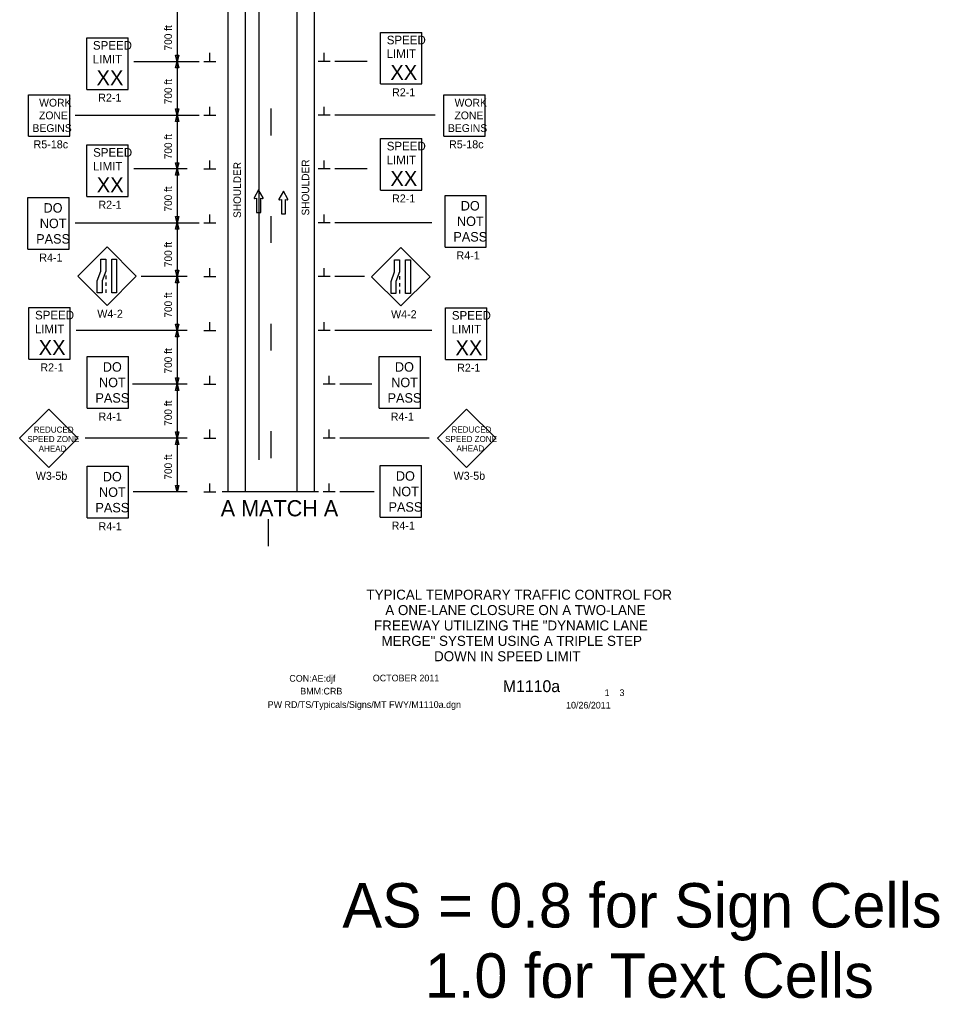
# Model space of a CAD drawing. Extents: x 15261 to 18126, y 1908 to 6555.
# Drawn here: x 15359 to 16214, y 1908 to 2818 of the extents above; entities that cross this region are included whole.
import ezdxf

# ---------------------------------------------------------------- set-up
doc = ezdxf.new("R2010")
doc.units = 0
for name, color, linetype in [('ALI_LEGAL_EX', 7, 'Continuous'), ('BORDER_SIGNAL_WO', 7, 'Continuous'), ('MT_SCRATCH_LEVEL_E', 7, 'Continuous'), ('PAVT_EDGE_EX', 7, 'Continuous'), ('TRAFFIC_SIGNS_PR', 7, 'Continuous'), ('TYPICAL_TEXT_DIMEN_PR', 7, 'Continuous')]:
    doc.layers.add(name, color=color, linetype=linetype)

msp = doc.modelspace()

# ---------------------------------------------------------------- linework, layer by layer
at = {"layer": 'ALI_LEGAL_EX'}
msp.add_line((15581.68, 3237.79), (15581.68, 2408.6), dxfattribs=at)
for points in [[(15593, 2735), (15593, 2710)], [(15593, 2635), (15593, 2610)], [(15593, 2535), (15593, 2510)], [(15593, 2435), (15593, 2410)], [(15590.81, 2328.27), (15590.81, 2353.27)]]:
    msp.add_lwpolyline(points, dxfattribs=at)
at = {"layer": 'MT_SCRATCH_LEVEL_E'}
for p, q in [((15581.51, 2659.29), (15577.39, 2652.05)), ((15585.65, 2652.05), (15581.51, 2659.29)), ((15604.48, 2658.02), (15600.37, 2650.78)), ((15608.63, 2650.78), (15604.48, 2658.02)), ((15577.88, 2651.37), (15579.65, 2651.68)), ((15579.65, 2651.68), (15579.65, 2638.43)), ((15583.4, 2638.43), (15583.4, 2651.68)), ((15583.4, 2651.68), (15585.17, 2651.37)), ((15600.85, 2650.1), (15602.63, 2650.41)), ((15602.63, 2650.41), (15602.63, 2637.16)), ((15606.37, 2637.16), (15606.37, 2650.41)), ((15606.37, 2650.41), (15608.15, 2650.1)), ((15579.65, 2638.43), (15583.4, 2638.43)), ((15602.63, 2637.16), (15606.37, 2637.16))]:
    msp.add_line(p, q, dxfattribs=at)
for centre, start, end in [((15577.8, 2651.83), 150.42484, 279.96381), ((15585.24, 2651.83), 260.03619, 29.77312), ((15600.78, 2650.56), 150.42484, 279.96381), ((15608.22, 2650.56), 260.03619, 29.77312)]:
    msp.add_arc(centre, 0.463, start, end, dxfattribs=at)
at = {"layer": 'PAVT_EDGE_EX'}
for p, q in [((15553, 3162.29), (15553, 2378.74)), ((15569, 3162.29), (15569, 2378.74)), ((15617, 3162.29), (15617, 2378.74)), ((15633, 3163.21), (15633, 2378.74))]:
    msp.add_line(p, q, dxfattribs=at)
at = {"layer": 'TRAFFIC_SIGNS_PR'}
for p, q in [((15694.86, 2805.71), (15733.26, 2805.71)), ((15694.86, 2757.71), (15694.86, 2805.71)), ((15733.26, 2757.71), (15733.26, 2805.71)), ((15421.69, 2800.74), (15460.09, 2800.74)), ((15421.69, 2752.74), (15421.69, 2800.74)), ((15460.09, 2752.74), (15460.09, 2800.74)), ((15694.86, 2757.71), (15733.26, 2757.71)), ((15367.49, 2709.37), (15367.49, 2747.77)), ((15367.49, 2747.77), (15405.89, 2747.77)), ((15405.89, 2709.37), (15405.89, 2747.77)), ((15421.69, 2752.74), (15460.09, 2752.74)), ((15753.7, 2709.37), (15753.7, 2747.77)), ((15753.7, 2747.77), (15792.1, 2747.77)), ((15792.1, 2709.37), (15792.1, 2747.77)), ((15367.49, 2709.37), (15405.89, 2709.37)), ((15421.89, 2701.27), (15460.29, 2701.27)), ((15421.89, 2653.27), (15421.89, 2701.27)), ((15460.29, 2653.27), (15460.29, 2701.27)), ((15694.86, 2707.12), (15733.26, 2707.12)), ((15694.86, 2659.12), (15694.86, 2707.12)), ((15733.26, 2659.12), (15733.26, 2707.12)), ((15753.7, 2709.37), (15792.1, 2709.37)), ((15694.86, 2659.12), (15733.26, 2659.12)), ((15366.92, 2604.2), (15366.92, 2652.2)), ((15366.92, 2652.2), (15405.32, 2652.2)), ((15405.32, 2604.2), (15405.32, 2652.2)), ((15421.89, 2653.27), (15460.29, 2653.27)), ((15754.76, 2606.14), (15754.76, 2654.14)), ((15754.76, 2654.14), (15793.16, 2654.14)), ((15793.16, 2606.14), (15793.16, 2654.14)), ((15366.92, 2604.2), (15405.32, 2604.2)), ((15440.58, 2606.28), (15413.42, 2579.12)), ((15467.73, 2579.12), (15440.58, 2606.28)), ((15713.65, 2605.8), (15686.5, 2578.65)), ((15740.81, 2578.65), (15713.65, 2605.8)), ((15754.76, 2606.14), (15793.16, 2606.14)), ((15413.42, 2579.12), (15440.58, 2551.97)), ((15439.33, 2579.62), (15439.33, 2576.42)), ((15440.58, 2551.97), (15467.73, 2579.12)), ((15686.5, 2578.65), (15713.65, 2551.49)), ((15712.41, 2579.14), (15712.41, 2575.94)), ((15713.65, 2551.49), (15740.81, 2578.65)), ((15439.33, 2573.22), (15439.33, 2570.02)), ((15439.33, 2566.82), (15439.33, 2563.62)), ((15712.41, 2572.74), (15712.41, 2569.54)), ((15712.41, 2566.34), (15712.41, 2563.14)), ((15367.92, 2550.12), (15406.32, 2550.12)), ((15367.92, 2502.12), (15367.92, 2550.12)), ((15406.32, 2502.12), (15406.32, 2550.12)), ((15755.36, 2549.85), (15793.76, 2549.85)), ((15755.36, 2501.85), (15755.36, 2549.85)), ((15793.76, 2501.85), (15793.76, 2549.85)), ((15367.92, 2502.12), (15406.32, 2502.12)), ((15422.01, 2456.41), (15422.01, 2504.41)), ((15422.01, 2504.41), (15460.41, 2504.41)), ((15460.41, 2456.41), (15460.41, 2504.41)), ((15693.58, 2456.41), (15693.58, 2504.41)), ((15693.58, 2504.41), (15731.98, 2504.41)), ((15731.98, 2456.41), (15731.98, 2504.41)), ((15755.36, 2501.85), (15793.76, 2501.85)), ((15422.01, 2456.41), (15460.41, 2456.41)), ((15693.58, 2456.41), (15731.98, 2456.41)), ((15774.79, 2455.71), (15747.64, 2428.56)), ((15801.94, 2428.56), (15774.79, 2455.71)), ((15386.43, 2455.66), (15359.28, 2428.51)), ((15413.58, 2428.51), (15386.43, 2455.66)), ((15359.28, 2428.51), (15386.43, 2401.35)), ((15386.43, 2401.35), (15413.58, 2428.51)), ((15747.64, 2428.56), (15774.79, 2401.4)), ((15774.79, 2401.4), (15801.94, 2428.56)), ((15422.01, 2354.46), (15422.01, 2402.46)), ((15422.01, 2402.46), (15460.41, 2402.46)), ((15460.41, 2354.46), (15460.41, 2402.46)), ((15694.47, 2355.09), (15694.47, 2403.09)), ((15694.47, 2403.09), (15732.87, 2403.09)), ((15732.87, 2355.09), (15732.87, 2403.09)), ((15422.01, 2354.46), (15460.41, 2354.46)), ((15694.47, 2355.09), (15732.87, 2355.09))]:
    msp.add_line(p, q, dxfattribs=at)
for points in [[(15439.33, 2594.86), (15439.33, 2583.68), (15435.99, 2574.8), (15435.99, 2563.62), (15431.49, 2563.62), (15431.49, 2574.8), (15434.84, 2583.68), (15434.84, 2594.86)], [(15449.47, 2594.86), (15449.47, 2563.62), (15444.97, 2563.62), (15444.97, 2594.86)], [(15712.41, 2594.38), (15712.41, 2583.2), (15709.06, 2574.32), (15709.06, 2563.14), (15704.57, 2563.14), (15704.57, 2574.32), (15707.91, 2583.2), (15707.91, 2594.38)], [(15722.54, 2594.38), (15722.54, 2563.14), (15718.05, 2563.14), (15718.05, 2594.38)]]:
    msp.add_lwpolyline(points, close=True, dxfattribs=at)
at = {"layer": 'TYPICAL_TEXT_DIMEN_PR'}
for p, q in [((15505.88, 2828.74), (15505.88, 2778.74)), ((15505.88, 2778.74), (15504.31, 2784.61)), ((15504.31, 2784.61), (15505.88, 2784.61)), ((15505.88, 2784.61), (15507.45, 2784.61)), ((15507.45, 2784.61), (15505.88, 2778.74)), ((15536.12, 2778.74), (15536.12, 2786.53)), ((15642.37, 2778.74), (15642.37, 2786.53)), ((15465.47, 2778.74), (15526.25, 2778.74)), ((15504.31, 2772.88), (15505.88, 2778.74)), ((15504.31, 2772.88), (15505.88, 2778.74)), ((15505.88, 2778.74), (15505.88, 2728.74)), ((15505.88, 2778.74), (15507.45, 2772.88)), ((15505.88, 2778.74), (15507.45, 2772.88)), ((15530.5, 2778.74), (15541.75, 2778.74)), ((15648, 2778.74), (15636.75, 2778.74)), ((15682.48, 2778.74), (15652.25, 2778.74)), ((15505.88, 2772.88), (15504.31, 2772.88)), ((15505.88, 2772.88), (15504.31, 2772.88)), ((15507.45, 2772.88), (15505.88, 2772.88)), ((15507.45, 2772.88), (15505.88, 2772.88)), ((15410.88, 2728.74), (15526.25, 2728.74)), ((15505.88, 2728.74), (15504.31, 2734.61)), ((15504.31, 2734.61), (15505.88, 2734.61)), ((15505.88, 2728.74), (15504.31, 2734.61)), ((15504.31, 2734.61), (15505.88, 2734.61)), ((15504.31, 2722.88), (15505.88, 2728.74)), ((15505.88, 2734.61), (15507.45, 2734.61)), ((15507.45, 2734.61), (15505.88, 2728.74)), ((15505.88, 2734.61), (15507.45, 2734.61)), ((15507.45, 2734.61), (15505.88, 2728.74)), ((15505.88, 2728.74), (15505.88, 2678.74)), ((15505.88, 2728.74), (15507.45, 2722.88)), ((15530.5, 2728.74), (15541.75, 2728.74)), ((15536.12, 2728.74), (15536.12, 2736.53)), ((15648, 2728.74), (15636.75, 2728.74)), ((15642.37, 2728.74), (15642.37, 2736.53)), ((15745.66, 2728.74), (15652.25, 2728.74)), ((15505.88, 2722.88), (15504.31, 2722.88)), ((15507.45, 2722.88), (15505.88, 2722.88)), ((15505.88, 2678.74), (15504.31, 2684.61)), ((15504.31, 2684.61), (15505.88, 2684.61)), ((15505.88, 2684.61), (15507.45, 2684.61)), ((15507.45, 2684.61), (15505.88, 2678.74)), ((15536.12, 2678.74), (15536.12, 2686.53)), ((15642.37, 2678.74), (15642.37, 2686.53)), ((15515.11, 2678.74), (15465.47, 2678.74)), ((15504.31, 2672.88), (15505.88, 2678.74)), ((15505.88, 2678.74), (15505.88, 2628.74)), ((15505.88, 2678.74), (15507.45, 2672.88)), ((15530.5, 2678.74), (15541.75, 2678.74)), ((15648, 2678.74), (15636.75, 2678.74)), ((15682.48, 2678.74), (15652.25, 2678.74)), ((15505.88, 2672.88), (15504.31, 2672.88)), ((15507.45, 2672.88), (15505.88, 2672.88)), ((15410.88, 2628.74), (15526.25, 2628.74)), ((15505.88, 2628.74), (15504.31, 2634.61)), ((15504.31, 2634.61), (15505.88, 2634.61)), ((15505.88, 2628.74), (15504.31, 2634.61)), ((15504.31, 2634.61), (15505.88, 2634.61)), ((15504.31, 2622.88), (15505.88, 2628.74)), ((15505.88, 2634.61), (15507.45, 2634.61)), ((15507.45, 2634.61), (15505.88, 2628.74)), ((15505.88, 2634.61), (15507.45, 2634.61)), ((15507.45, 2634.61), (15505.88, 2628.74)), ((15505.88, 2628.74), (15505.88, 2578.74)), ((15505.88, 2628.74), (15507.45, 2622.88)), ((15530.5, 2628.74), (15541.75, 2628.74)), ((15536.12, 2628.74), (15536.12, 2636.53)), ((15648, 2628.74), (15636.75, 2628.74)), ((15642.37, 2628.74), (15642.37, 2636.53)), ((15742.5, 2628.74), (15652.25, 2628.74)), ((15505.88, 2622.88), (15504.31, 2622.88)), ((15507.45, 2622.88), (15505.88, 2622.88)), ((15505.88, 2578.74), (15504.31, 2584.61)), ((15504.31, 2584.61), (15505.88, 2584.61)), ((15505.88, 2584.61), (15507.45, 2584.61)), ((15507.45, 2584.61), (15505.88, 2578.74)), ((15536.12, 2578.74), (15536.12, 2586.53)), ((15642.37, 2578.74), (15642.37, 2586.53)), ((15515.11, 2578.74), (15472.22, 2578.74)), ((15504.31, 2572.88), (15505.88, 2578.74)), ((15505.88, 2578.74), (15507.45, 2572.88)), ((15505.88, 2578.74), (15505.88, 2528.74)), ((15530.5, 2578.74), (15541.75, 2578.74)), ((15648, 2578.74), (15636.75, 2578.74)), ((15679.85, 2578.74), (15652.25, 2578.74)), ((15505.88, 2572.88), (15504.31, 2572.88)), ((15507.45, 2572.88), (15505.88, 2572.88)), ((15515.11, 2528.74), (15411.99, 2528.74)), ((15505.88, 2528.74), (15504.31, 2534.61)), ((15504.31, 2534.61), (15505.88, 2534.61)), ((15504.31, 2522.88), (15505.88, 2528.74)), ((15505.88, 2534.61), (15507.45, 2534.61)), ((15507.45, 2534.61), (15505.88, 2528.74)), ((15505.88, 2528.74), (15507.45, 2522.88)), ((15505.88, 2528.74), (15505.88, 2478.74)), ((15530.5, 2528.74), (15541.75, 2528.74)), ((15536.12, 2528.74), (15536.12, 2536.53)), ((15648, 2528.74), (15636.75, 2528.74)), ((15642.37, 2528.74), (15642.37, 2536.53)), ((15742.5, 2528.74), (15652.25, 2528.74)), ((15505.88, 2522.88), (15504.31, 2522.88)), ((15507.45, 2522.88), (15505.88, 2522.88)), ((15505.88, 2478.74), (15504.31, 2484.61)), ((15504.31, 2484.61), (15505.88, 2484.61)), ((15505.88, 2484.61), (15507.45, 2484.61)), ((15507.45, 2484.61), (15505.88, 2478.74)), ((15536.12, 2478.74), (15536.12, 2486.53)), ((15647.13, 2478.74), (15647.13, 2486.53)), ((15515.11, 2478.74), (15464.24, 2478.74)), ((15504.31, 2472.88), (15505.88, 2478.74)), ((15505.88, 2478.74), (15507.45, 2472.88)), ((15505.88, 2478.74), (15505.88, 2428.74)), ((15530.5, 2478.74), (15541.75, 2478.74)), ((15652.75, 2478.74), (15641.5, 2478.74)), ((15686.65, 2478.74), (15657.07, 2478.74)), ((15505.88, 2472.88), (15504.31, 2472.88)), ((15507.45, 2472.88), (15505.88, 2472.88)), ((15515.11, 2428.74), (15420.33, 2428.74)), ((15505.88, 2428.74), (15504.31, 2434.61)), ((15504.31, 2434.61), (15505.88, 2434.61)), ((15504.31, 2422.88), (15505.88, 2428.74)), ((15505.88, 2434.61), (15507.45, 2434.61)), ((15507.45, 2434.61), (15505.88, 2428.74)), ((15505.88, 2428.74), (15507.45, 2422.88)), ((15505.88, 2428.74), (15505.88, 2378.74)), ((15530.5, 2428.74), (15541.75, 2428.74)), ((15536.12, 2428.74), (15536.12, 2436.53)), ((15652.75, 2428.74), (15641.5, 2428.74)), ((15647.13, 2428.74), (15647.13, 2436.53)), ((15740.14, 2428.74), (15657.07, 2428.74)), ((15505.88, 2422.88), (15504.31, 2422.88)), ((15507.45, 2422.88), (15505.88, 2422.88)), ((15505.88, 2378.74), (15504.31, 2384.61)), ((15504.31, 2384.61), (15505.88, 2384.61)), ((15505.88, 2384.61), (15507.45, 2384.61)), ((15507.45, 2384.61), (15505.88, 2378.74)), ((15536.12, 2378.74), (15536.12, 2386.53)), ((15647.13, 2378.74), (15647.13, 2386.53)), ((15515.11, 2378.74), (15464.95, 2378.74)), ((15530.5, 2378.74), (15541.75, 2378.74)), ((15637.19, 2378.74), (15547.76, 2378.74)), ((15652.75, 2378.74), (15641.5, 2378.74)), ((15688.96, 2378.74), (15657.07, 2378.74))]:
    msp.add_line(p, q, dxfattribs=at)

# ---------------------------------------------------------------- texts
at = {"layer": 'BORDER_SIGNAL_WO'}
for s, height, p in [('TYPICAL TEMPORARY TRAFFIC CONTROL FOR', 9.3, (15681.73, 2278.54)), ('A ONE-LANE CLOSURE ON A TWO-LANE', 9.3, (15699.24, 2264.24)), ('FREEWAY UTILIZING THE "DYNAMIC LANE', 9.3, (15688.74, 2249.94)), ('MERGE" SYSTEM USING A TRIPLE STEP', 9.3, (15695.73, 2235.64)), ('DOWN IN SPEED LIMIT', 9.3, (15744.6, 2221.34)), ('CON:AE:djf  ', 6.2, (15610.05, 2202.35)), ('    OCTOBER 2011    ', 6.2, (15678.44, 2202.63)), ('    M1110a   ', 11, (15792.22, 2192.67)), ('BMM:CRB   ', 6.2, (15620.17, 2190.46)), (' 1    3 ', 6.2, (15900.81, 2188.99)), ('PW RD/TS/Typicals/Signs/MT FWY/M1110a.dgn      ', 6.2, (15589.92, 2178)), ('10/26/2011    ', 6.2, (15867.29, 2177.42)), ('AS = 0.8 for Sign Cells', 41.2877, (15659.37, 1973.92)), ('     1.0 for Text Cells', 41.2877, (15659.37, 1908.64))]:
    msp.add_text(s, height=height, dxfattribs=at).set_placement(p)
at = {"layer": 'TRAFFIC_SIGNS_PR'}
for s, height, p in [('SPEED', 8, (15700.63, 2794.58)), ('SPEED', 8, (15427.45, 2789.6)), ('LIMIT', 8, (15427.29, 2776.8)), ('LIMIT', 8, (15700.47, 2781.78)), ('XX', 14.031, (15703.97, 2761.47)), ('XX', 14.031, (15430.8, 2756.5)), ('R2-1', 7.44, (15432.36, 2741.3)), ('R2-1', 7.44, (15705.54, 2746.27)), ('WORK', 7.217, (15377.49, 2736.74)), ('WORK', 7.217, (15763.7, 2736.74)), ('ZONE', 7.217, (15377.37, 2724.93)), ('ZONE', 7.217, (15763.58, 2724.93)), ('BEGINS', 7.217, (15371.3, 2713.12)), ('BEGINS', 7.217, (15757.51, 2713.12)), ('R5-18c', 7.44, (15372.3, 2697.93)), ('SPEED', 8, (15700.63, 2695.99)), ('R5-18c', 7.44, (15758.51, 2697.93)), ('SPEED', 8, (15427.66, 2690.14)), ('LIMIT', 8, (15427.5, 2677.34)), ('LIMIT', 8, (15700.47, 2683.19)), ('XX', 14.031, (15703.97, 2662.88)), ('XX', 14.031, (15431, 2657.03)), ('DO', 8.8, (15381.55, 2638.2)), ('R2-1', 7.44, (15432.57, 2641.83)), ('R2-1', 7.44, (15705.54, 2647.68)), ('DO', 8.8, (15769.39, 2640.15)), ('NOT', 8.8, (15378.07, 2623.8)), ('NOT', 8.8, (15765.9, 2625.75)), ('PASS', 8.8, (15762.55, 2611.35)), ('PASS', 8.8, (15374.72, 2609.4)), ('R4-1', 7.44, (15765.44, 2594.71)), ('R4-1', 7.44, (15377.6, 2592.76)), ('SPEED', 8, (15373.68, 2538.98)), ('W4-2', 7.44, (15431.53, 2540.53)), ('W4-2', 7.44, (15704.61, 2540.06)), ('SPEED', 8, (15761.13, 2538.71)), ('LIMIT', 8, (15373.52, 2526.18)), ('LIMIT', 8, (15760.97, 2525.91)), ('XX', 14.031, (15377.03, 2505.88)), ('XX', 14.031, (15764.47, 2505.61)), ('R2-1', 7.44, (15378.59, 2490.68)), ('DO', 8.8, (15436.65, 2490.41)), ('DO', 8.8, (15708.21, 2490.41)), ('R2-1', 7.44, (15766.04, 2490.41)), ('NOT', 8.8, (15433.16, 2476.01)), ('NOT', 8.8, (15704.73, 2476.01)), ('PASS', 8.8, (15429.81, 2461.62)), ('PASS', 8.8, (15701.38, 2461.62)), ('R4-1', 7.44, (15432.69, 2444.97)), ('R4-1', 7.44, (15704.26, 2444.97)), ('REDUCED', 5.6, (15372.49, 2433.81)), ('REDUCED', 5.6, (15760.85, 2433.87)), ('SPEED ZONE', 5.6, (15366.48, 2425.01)), ('SPEED ZONE', 5.6, (15754.84, 2425.07)), ('AHEAD', 5.6, (15377.04, 2416.21)), ('AHEAD', 5.6, (15765.4, 2416.27)), ('W3-5b', 7.44, (15374.38, 2389.91)), ('DO', 8.8, (15436.65, 2388.46)), ('DO', 8.8, (15709.1, 2389.09)), ('W3-5b', 7.44, (15762.74, 2389.96)), ('NOT', 8.8, (15433.16, 2374.06)), ('NOT', 8.8, (15705.61, 2374.69)), ('PASS', 8.8, (15429.81, 2359.66)), ('PASS', 8.8, (15702.26, 2360.29)), ('R4-1', 7.44, (15432.69, 2343.02)), ('R4-1', 7.44, (15705.14, 2343.65))]:
    msp.add_text(s, height=height, dxfattribs=at).set_placement(p)
at = {"layer": 'TYPICAL_TEXT_DIMEN_PR'}
for s, p in [('700 ft', (15500.92, 2788.91)), ('700 ft', (15500.92, 2738.91)), ('700 ft', (15500.92, 2687.81)), ('SHOULDER', (15565.1, 2633.23)), ('SHOULDER', (15628.53, 2635.54)), ('700 ft', (15500.92, 2639.18)), ('700 ft', (15500.92, 2587.59)), ('700 ft', (15500.92, 2540.61)), ('700 ft', (15500.92, 2488.69)), ('700 ft', (15500.92, 2440.06)), ('700 ft', (15500.92, 2390.11))]:
    msp.add_text(s, height=7, rotation=90, dxfattribs=at).set_placement(p)
msp.add_text('A MATCH A', height=15, dxfattribs=at).set_placement((15546.27, 2356.02))

doc.saveas('drawing.dxf')
